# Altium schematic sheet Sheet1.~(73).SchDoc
size A
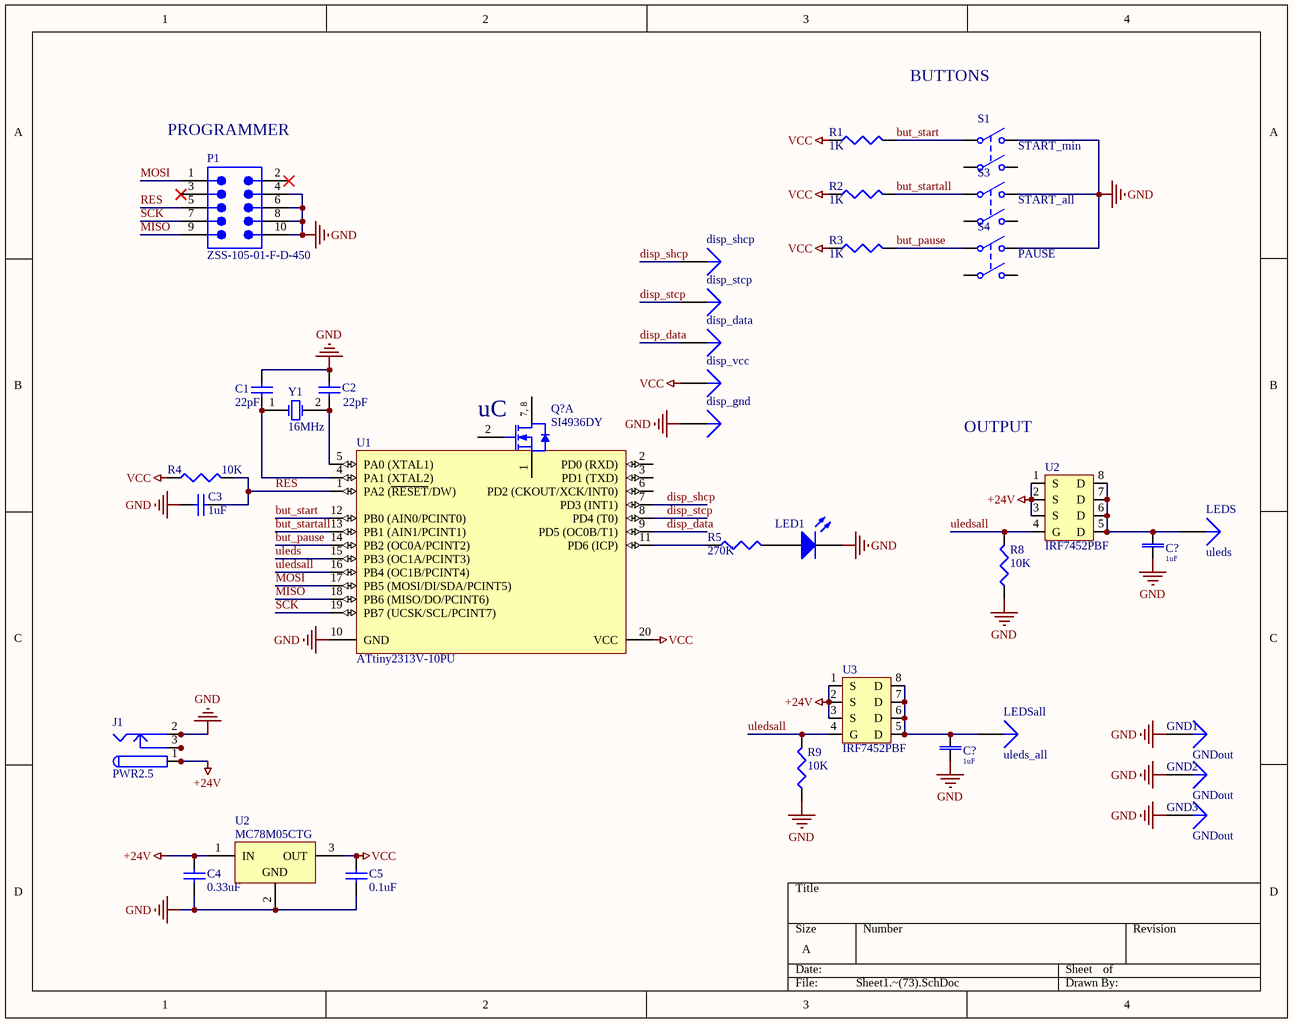
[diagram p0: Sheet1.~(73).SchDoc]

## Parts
(Parts that share a designator on the sheet are numbered #1, #2 ... from top to bottom, then left to right.)
C1  value 22pF  [CAPC1608L]  (hidden comment: Cap Semi)
C2  value 22pF  [CAPC1608L]  (hidden comment: Cap Semi)
C3  value 1uF  [CAPC1608L]  (hidden comment: Cap Semi)
C4  value 0.33uF  [CAPC1608L]  (hidden comment: Cap Semi)
C5  value 0.1uF  [CAPC1608L]  (hidden comment: Cap Semi)
C?#1  value 1uF  [CAPC3216L]  (hidden comment: Cap Semi)
C?#2  value 1uF  [CAPC3216L]  (hidden comment: Cap Semi)
disp_data  uleds_all  [PIN1]  (value not drawn)
disp_gnd  uleds_all  [PIN1]  (value not drawn)
disp_shcp  uleds_all  [PIN1]  (value not drawn)
disp_stcp  uleds_all  [PIN1]  (value not drawn)
disp_vcc  uleds_all  [PIN1]  (value not drawn)
GND1  GNDout  [PIN1]
GND2  GNDout  [PIN1]
GND3  GNDout  [PIN1]
J1  PWR2.5  [PCBComponent_1]
LED1  151051YS04000  [Type 5mm]  (value not drawn)
LEDS  uleds  [PIN1]
LEDSall  uleds_all  [PIN1]
P1  ZSS-105-01-F-D-450  [SMTC-ZSS-105-01-X-D-450]
Q?  SI4936DY  [SO-8_N]  (part A of 2)
R1  value 1K  [CAPC1608L]  (hidden comment: Res3)
R2  value 1K  [CAPC1608L]  (hidden comment: Res3)
R3  value 1K  [CAPC1608L]  (hidden comment: Res3)
R4  value 10K  [CAPC1608L]  (hidden comment: Res3)
R5  value 270K  [CAPC1608L]  (hidden comment: Res3)
R8  value 10K  [CAPC1608L]  (hidden comment: Res3)
R9  value 10K  [CAPC1608L]  (hidden comment: Res3)
S1  START_min  [key]
S3  START_all  [key]
S4  PAUSE  [key]
U1  ATtiny2313V-10PU  [20P3]
U2#1  IRF7452PBF  [SO-8_M]
U2#2  MC78M05CTG  [TO220]
U3  IRF7452PBF  [SO-8_M]
Y1  16MHz  [PCBComponent_1 - duplicate]

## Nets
+24V: C4.2 J1.1 J1.1A J1.1B U2#1.1(S) U2#1.2(S) U2#1.3(S) U2#2.1(IN) U3.1(S) U3.2(S) U3.3(S)
GND: C1.1 C2.1 C3.2 C4.1 C5.1 C?#1.2 C?#2.2 disp_gnd.1 GND1.1 GND2.1 GND3.1 J1.2 J1.2A J1.2B LED1.1(K) P1.4 P1.6 P1.8 P1.10 R8.1 R9.1 S1.2(NO1) S3.2(NO1) S4.2(NO1) U1.10(GND) U2#2.2(GND)
VCC: C5.2 disp_vcc.1 R1.1 R2.1 R3.1 R4.1 U1.20(VCC) U2#2.3(OUT)
but_pause: R3.2 S4.1(COMMON1) U1.14(PB2_(OC0A/PCINT2))
but_start: R1.2 S1.1(COMMON1) U1.12(PB0_(AIN0/PCINT0))
but_startall: R2.2 S3.1(COMMON1) U1.13(PB1_(AIN1/PCINT1))
disp_data: disp_data.1 U1.9(PD5_(OC0B/T1))
disp_shcp: disp_shcp.1 U1.7(PD3_(INT1))
disp_stcp: disp_stcp.1 U1.8(PD4_(T0))
MISO: P1.9 U1.18(PB6_(MISO/DO/PCINT6))
MOSI: P1.1 U1.17(PB5_(MOSI/DI/SDA/PCINT5))
RES: C3.1 P1.5 R4.2 U1.1(PA2_(~{RESET}/DW))
SCK: P1.7 U1.19(PB7_(UCSK/SCL/PCINT7))
uleds: U1.15(PB3_(OC1A/PCINT3))
uledsall: R8.2 R9.2 U1.16(PB4_(OC1B/PCINT4)) U2#1.4(G) U3.4(G)
NetC1_2: C1.2 U1.4(PA1_(XTAL2)) Y1.1(OSC1)
NetC2_2: C2.2 U1.5(PA0_(XTAL1)) Y1.2(OSC2)
NetC?#1_1: C?#1.1 LEDS.1 U2#1.5(D) U2#1.6(D) U2#1.7(D) U2#1.8(D)
NetC?#2_1: C?#2.1 LEDSall.1 U3.5(D) U3.6(D) U3.7(D) U3.8(D)
NetJ1_3: J1.3 J1.3A J1.3B
NetLED1_2: LED1.2(A) R5.2
NetQ?_7: Q?.7(D) Q?.8(D)
NetR5_1: R5.1 U1.11(PD6_(ICP))

Not connected (* = marked no-connect by the designer): P1 2* 3*; Q? 1(S) 2(G); S1 3(COMMON2) 4(NO2); S3 3(COMMON2) 4(NO2); S4 3(COMMON2) 4(NO2); U1 2(PD0_(RXD)) 3(PD1_(TXD)) 6(PD2_(CKOUT/XCK/INT0))

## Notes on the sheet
- BUTTONS
- (near P1) PROGRAMMER
- (near Q?) uC
- OUTPUT

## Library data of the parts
C1-C5 C?#1 C?#2 = Cap Semi: Capacitor (Semiconductor SIM Model)
disp_data disp_gnd disp_shcp disp_stcp disp_vcc GND1-GND3 LEDS LEDSall = Plug
J1 = PWR2.5: Low Voltage Power Supply Connector
LED1 = CMP-1488-00010-1: THT LED round mono-color color lens, WL-TMRW, Yellow; Manufacturer: Wuerth Elektronik
P1 = CMP-1024-00461-1: Manufacturer: Samtec; Pitch: 2.54 mm
Q? = SI4936DY: Dual N-Channel 30V (D-S)  MOSFET
R1-R5 R8 R9 = Res3: Resistor
S1 S3 S4 = SW-DPST: Double-Pole, Single-Throw Switch
U1 = CMP-0093-00017-1: Low Power tinyAVR® 8-Bit Microcontroller, 2K Flash Memory, 10MHz, Industrial Temperature, 20-Lead PDIP, Pb-Free
U2#2 = CMP-0244-00483-1: Positive Voltage Regulator, 5V, 3-Pin TO-220
Y1 = XTAL: Crystal Oscillator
